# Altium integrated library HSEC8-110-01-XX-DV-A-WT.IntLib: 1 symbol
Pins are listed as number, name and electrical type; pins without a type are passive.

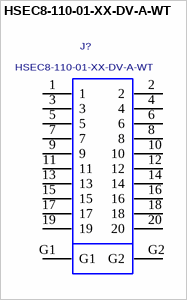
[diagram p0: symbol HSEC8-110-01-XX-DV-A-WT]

## HSEC8-110-01-XX-DV-A-WT
designator J?
0.8MM HIGH SPEED ASSEMBLY.; MANUFACTURER: SAMTEC
footprint HSEC8-110-01-XX-DV-A-WT
pins: 1, 2, 3, 4, 5, 6, 7, 8, 9, 10, 11, 12, 13, 14, 15, 16, 17, 18, 19, 20, G1, G2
